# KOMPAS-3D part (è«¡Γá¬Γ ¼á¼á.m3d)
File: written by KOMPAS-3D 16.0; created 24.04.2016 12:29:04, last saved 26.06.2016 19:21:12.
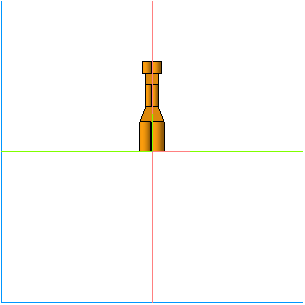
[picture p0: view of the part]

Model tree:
1. Эскиз:1
2. Операция выдавливания:1
     Расстояние 1 = 0.3; Расстояние 2 = 5; Угол 2 = 2
3. Эскиз:2
4. Операция вращения:1
     Угол 1 = 180; Угол 2 = 360
5. Эскиз:3
6. Операция вращения:2
     Угол 1 = 180; Угол 2 = 360
7. Эскиз:4
8. Операция вращения:3
     Угол 1 = 180; Угол 2 = 360
9. Эскиз:5
10. Операция вращения:4
     Угол 1 = 180; Угол 2 = 360
11. Эскиз:6
12. Операция вращения:5
     Угол 1 = 180; Угол 2 = 360
13. Эскиз:7
14. Операция вращения:6
     Угол 1 = 180; Угол 2 = 360
15. Эскиз:9
16. Вырезать элемент выдавливания:1
     Расстояние 1 = 3
17. Эскиз:10
18. Вырезать элемент выдавливания:2
     Расстояние 1 = 5
19. Эскиз:11
20. Вырезать элемент выдавливания:3
     Расстояние 1 = 5
21. Скругление:1
     Радиус = 1
22. Эскиз:12
23. Вырезать элемент выдавливания:4
     Расстояние 1 = 0.6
